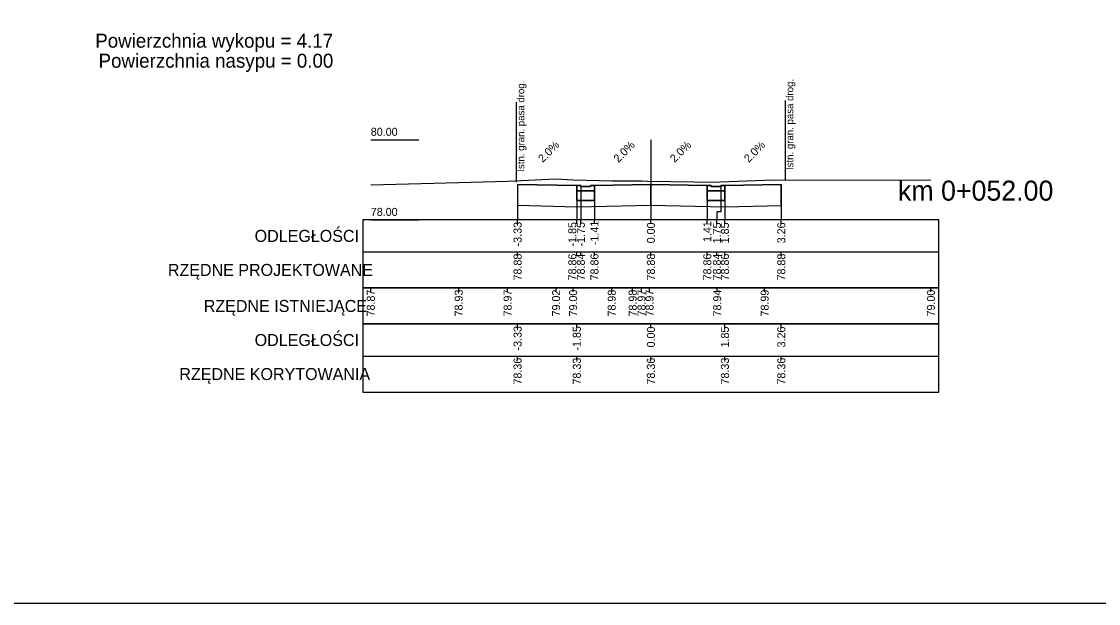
# Model space of a CAD drawing. Extents: x 7492871 to 7493499, y 5802964 to 5802992.
# Drawn here: x 7493013.99 to 7493040.9, y 5802963.88 to 5802978.41 of the extents above; entities that cross this region are included whole.
import ezdxf

# ---------------------------------------------------------------- set-up
doc = ezdxf.new("R2010")
doc.units = 0
for name, color, linetype in [('_wydruk', 7, 'Continuous'), ('d_pop_nasyp_opis', 7, 'Continuous'), ('d_pop_wykop_opis', 7, 'Continuous'), ('opisy_ramki_pop', 7, 'Continuous'), ('pop_comp_kostka', 7, 'Continuous'), ('pop_comp_lawa', 7, 'Continuous'), ('pop_comp_scieralna', 7, 'Continuous'), ('pop_granica_istn', 7, 'Continuous'), ('pop_opis', 7, 'Continuous'), ('pop_os', 7, 'Continuous'), ('pop_pikietaz', 7, 'Continuous'), ('pop_teren', 7, 'Continuous')]:
    doc.layers.add(name, color=color, linetype=linetype)

msp = doc.modelspace()

# ---------------------------------------------------------------- linework, layer by layer
msp.add_lwpolyline([(7493026.385, 5802974.344), (7493027.866, 5802974.314), (7493027.966, 5802974.314), (7493027.967, 5802974.294), (7493028.206, 5802974.294), (7493028.207, 5802974.314), (7493028.307, 5802974.314), (7493029.717, 5802974.343), (7493031.127, 5802974.314), (7493031.227, 5802974.314), (7493031.228, 5802974.294), (7493031.467, 5802974.294), (7493031.468, 5802974.314), (7493031.568, 5802974.314), (7493032.977, 5802974.343)])
at = {"layer": '_wydruk'}
msp.add_lwpolyline([(7492871.369, 5802992.281), (7493499.283, 5802992.281), (7493499.283, 5802963.881), (7492871.369, 5802963.881)], close=True, dxfattribs=at)
at = {"layer": 'opisy_ramki_pop'}
for points in [[(7493026.385, 5802973.824), (7493026.385, 5802973.659), (7493026.385, 5802973.659), (7493026.385, 5802973.459)], [(7493027.866, 5802973.785), (7493027.866, 5802973.659), (7493027.866, 5802973.659), (7493027.866, 5802973.459)], [(7493029.717, 5802973.823), (7493029.717, 5802973.659), (7493029.717, 5802973.659), (7493029.717, 5802973.459)], [(7493031.568, 5802973.785), (7493031.568, 5802973.659), (7493031.568, 5802973.659), (7493031.568, 5802973.459)], [(7493032.977, 5802973.822), (7493032.977, 5802973.659), (7493032.977, 5802973.659), (7493032.977, 5802973.459)]]:
    msp.add_lwpolyline(points, dxfattribs=at)
at = {"layer": 'pop_comp_kostka'}
for p, q in [((7493027.966, 5802974.314), (7493027.866, 5802974.314)), ((7493027.866, 5802974.314), (7493027.866, 5802974.184)), ((7493027.967, 5802974.294), (7493027.966, 5802974.314)), ((7493028.206, 5802974.294), (7493027.967, 5802974.294)), ((7493028.207, 5802974.314), (7493028.206, 5802974.294)), ((7493028.307, 5802974.314), (7493028.207, 5802974.314)), ((7493028.307, 5802974.184), (7493028.307, 5802974.314)), ((7493031.227, 5802974.314), (7493031.127, 5802974.314)), ((7493031.127, 5802974.314), (7493031.127, 5802974.184)), ((7493031.228, 5802974.294), (7493031.227, 5802974.314)), ((7493031.467, 5802974.294), (7493031.228, 5802974.294)), ((7493031.468, 5802974.314), (7493031.467, 5802974.294)), ((7493031.568, 5802974.314), (7493031.468, 5802974.314)), ((7493031.568, 5802974.184), (7493031.568, 5802974.314)), ((7493027.866, 5802974.184), (7493028.307, 5802974.184)), ((7493031.127, 5802974.184), (7493031.568, 5802974.184))]:
    msp.add_line(p, q, dxfattribs=at)
at = {"layer": 'pop_comp_lawa'}
for p, q in [((7493028.307, 5802974.184), (7493027.866, 5802974.184)), ((7493027.866, 5802974.184), (7493027.866, 5802973.944)), ((7493028.307, 5802973.944), (7493028.307, 5802974.184)), ((7493031.568, 5802974.184), (7493031.127, 5802974.184)), ((7493031.127, 5802974.184), (7493031.127, 5802973.944)), ((7493031.568, 5802973.944), (7493031.568, 5802974.184)), ((7493027.866, 5802973.944), (7493028.307, 5802973.944)), ((7493031.127, 5802973.944), (7493031.568, 5802973.944))]:
    msp.add_line(p, q, dxfattribs=at)
at = {"layer": 'pop_comp_scieralna'}
for p, q in [((7493027.866, 5802974.314), (7493026.385, 5802974.344)), ((7493026.385, 5802974.344), (7493026.385, 5802973.824)), ((7493027.866, 5802973.944), (7493027.866, 5802974.314)), ((7493029.717, 5802974.343), (7493028.307, 5802974.314)), ((7493028.307, 5802974.314), (7493028.307, 5802973.944)), ((7493029.717, 5802973.823), (7493029.717, 5802974.343)), ((7493031.127, 5802974.314), (7493029.717, 5802974.343)), ((7493029.717, 5802974.343), (7493029.717, 5802973.823)), ((7493031.127, 5802973.944), (7493031.127, 5802974.314)), ((7493032.977, 5802974.343), (7493031.568, 5802974.314)), ((7493031.568, 5802974.314), (7493031.568, 5802973.944)), ((7493032.977, 5802973.822), (7493032.977, 5802974.343)), ((7493026.385, 5802973.824), (7493027.866, 5802973.785)), ((7493028.307, 5802973.944), (7493027.866, 5802973.944)), ((7493027.866, 5802973.785), (7493029.717, 5802973.823)), ((7493029.717, 5802973.823), (7493031.568, 5802973.785)), ((7493031.568, 5802973.944), (7493031.127, 5802973.944)), ((7493031.568, 5802973.785), (7493032.977, 5802973.822))]:
    msp.add_line(p, q, dxfattribs=at)
at = {"layer": 'pop_granica_istn'}
for p, q in [((7493033.079, 5802974.943), (7493033.079, 5802976.443)), ((7493026.357, 5802974.901), (7493026.357, 5802976.401)), ((7493026.357, 5802974.401), (7493026.357, 5802974.901)), ((7493033.079, 5802974.443), (7493033.079, 5802974.943))]:
    msp.add_line(p, q, dxfattribs=at)
at = {"layer": 'pop_opis'}
for p, q in [((7493022.717, 5802975.459), (7493023.917, 5802975.459)), ((7493022.517, 5802973.459), (7493022.517, 5802971.759)), ((7493022.517, 5802973.459), (7493022.517, 5802971.759)), ((7493022.517, 5802973.459), (7493022.517, 5802971.759)), ((7493022.517, 5802973.459), (7493022.517, 5802971.759)), ((7493022.717, 5802973.459), (7493023.917, 5802973.459)), ((7493026.385, 5802973.359), (7493026.385, 5802973.459)), ((7493027.866, 5802973.359), (7493027.866, 5802973.459)), ((7493027.967, 5802973.359), (7493027.967, 5802973.459)), ((7493028.307, 5802973.359), (7493028.307, 5802973.459)), ((7493029.717, 5802973.359), (7493029.717, 5802973.459)), ((7493031.127, 5802973.359), (7493031.127, 5802973.459)), ((7493031.368, 5802973.359), (7493031.368, 5802973.459)), ((7493031.568, 5802973.359), (7493031.568, 5802973.459)), ((7493032.977, 5802973.359), (7493032.977, 5802973.459)), ((7493022.517, 5802972.659), (7493036.917, 5802972.659)), ((7493022.517, 5802972.659), (7493036.917, 5802972.659)), ((7493022.517, 5802972.659), (7493036.917, 5802972.659)), ((7493022.517, 5802972.659), (7493036.917, 5802972.659)), ((7493026.385, 5802972.559), (7493026.385, 5802972.659)), ((7493027.866, 5802972.559), (7493027.866, 5802972.659)), ((7493027.967, 5802972.559), (7493027.967, 5802972.659)), ((7493028.307, 5802972.559), (7493028.307, 5802972.659)), ((7493029.717, 5802972.559), (7493029.717, 5802972.659)), ((7493031.127, 5802972.559), (7493031.127, 5802972.659)), ((7493031.368, 5802972.559), (7493031.368, 5802972.659)), ((7493031.568, 5802972.559), (7493031.568, 5802972.659)), ((7493032.977, 5802972.559), (7493032.977, 5802972.659)), ((7493022.517, 5802971.759), (7493022.517, 5802970.859)), ((7493022.717, 5802971.659), (7493022.717, 5802971.759)), ((7493024.913, 5802971.659), (7493024.913, 5802971.759)), ((7493026.136, 5802971.659), (7493026.136, 5802971.759)), ((7493027.348, 5802971.659), (7493027.348, 5802971.759)), ((7493027.773, 5802971.659), (7493027.773, 5802971.759)), ((7493028.738, 5802971.659), (7493028.738, 5802971.759)), ((7493029.262, 5802971.659), (7493029.262, 5802971.759)), ((7493029.483, 5802971.659), (7493029.483, 5802971.759)), ((7493029.683, 5802971.659), (7493029.683, 5802971.759)), ((7493031.375, 5802971.659), (7493031.375, 5802971.759)), ((7493032.561, 5802971.659), (7493032.561, 5802971.759)), ((7493036.717, 5802971.659), (7493036.717, 5802971.759)), ((7493022.517, 5802970.859), (7493022.517, 5802969.159)), ((7493026.385, 5802970.759), (7493026.385, 5802970.859)), ((7493027.866, 5802970.759), (7493027.866, 5802970.859)), ((7493029.717, 5802970.759), (7493029.717, 5802970.859)), ((7493031.568, 5802970.759), (7493031.568, 5802970.859)), ((7493032.977, 5802970.759), (7493032.977, 5802970.859)), ((7493022.517, 5802970.059), (7493036.917, 5802970.059)), ((7493026.385, 5802969.959), (7493026.385, 5802970.059)), ((7493027.866, 5802969.959), (7493027.866, 5802970.059)), ((7493029.717, 5802969.959), (7493029.717, 5802970.059)), ((7493031.568, 5802969.959), (7493031.568, 5802970.059)), ((7493032.977, 5802969.959), (7493032.977, 5802970.059))]:
    msp.add_line(p, q, dxfattribs=at)
for points in [[(7493026.385, 5802974.344), (7493026.385, 5802973.659), (7493026.385, 5802973.659), (7493026.385, 5802973.459)], [(7493027.866, 5802974.314), (7493027.866, 5802973.659), (7493027.866, 5802973.659), (7493027.866, 5802973.459)], [(7493027.967, 5802974.294), (7493027.967, 5802973.659), (7493027.967, 5802973.659), (7493027.967, 5802973.459)], [(7493028.307, 5802974.314), (7493028.307, 5802973.659), (7493028.307, 5802973.659), (7493028.307, 5802973.459)], [(7493029.717, 5802974.343), (7493029.717, 5802973.659), (7493029.717, 5802973.659), (7493029.717, 5802973.459)], [(7493031.127, 5802974.314), (7493031.127, 5802973.659), (7493031.127, 5802973.659), (7493031.127, 5802973.459)], [(7493031.467, 5802974.294), (7493031.467, 5802973.659), (7493031.368, 5802973.659), (7493031.368, 5802973.459)], [(7493031.568, 5802974.314), (7493031.568, 5802973.659), (7493031.568, 5802973.659), (7493031.568, 5802973.459)], [(7493032.977, 5802974.343), (7493032.977, 5802973.659), (7493032.977, 5802973.659), (7493032.977, 5802973.459)]]:
    msp.add_lwpolyline(points, dxfattribs=at)
for points in [[(7493022.517, 5802973.459), (7493022.517, 5802971.759), (7493036.917, 5802971.759), (7493036.917, 5802973.459)], [(7493022.517, 5802973.459), (7493022.517, 5802971.759), (7493036.917, 5802971.759), (7493036.917, 5802973.459)], [(7493022.517, 5802973.459), (7493022.517, 5802971.759), (7493036.917, 5802971.759), (7493036.917, 5802973.459)], [(7493022.517, 5802973.459), (7493022.517, 5802971.759), (7493036.917, 5802971.759), (7493036.917, 5802973.459)], [(7493022.517, 5802971.759), (7493022.517, 5802970.859), (7493036.917, 5802970.859), (7493036.917, 5802971.759)], [(7493022.517, 5802970.859), (7493022.517, 5802969.159), (7493036.917, 5802969.159), (7493036.917, 5802970.859)]]:
    msp.add_lwpolyline(points, close=True, dxfattribs=at)
at = {"layer": 'pop_os'}
msp.add_line((7493029.717, 5802975.459), (7493029.717, 5802973.459), dxfattribs=at)
at = {"layer": 'pop_teren'}
msp.add_lwpolyline([(7493022.717, 5802974.332), (7493024.913, 5802974.389), (7493026.136, 5802974.428), (7493027.348, 5802974.484), (7493027.773, 5802974.455), (7493028.738, 5802974.438), (7493029.262, 5802974.436), (7493029.483, 5802974.433), (7493029.631, 5802974.429), (7493031.375, 5802974.402), (7493031.448, 5802974.408), (7493032.561, 5802974.448), (7493036.717, 5802974.458)], dxfattribs=at)

# ---------------------------------------------------------------- texts
at = {"layer": 'd_pop_nasyp_opis'}
msp.add_text('Powierzchnia nasypu = 0.00', height=0.35, dxfattribs=at).set_placement((7493015.912, 5802977.259))
at = {"layer": 'd_pop_wykop_opis'}
msp.add_text('Powierzchnia wykopu = 4.17', height=0.35, dxfattribs=at).set_placement((7493015.829, 5802977.759))
at = {"layer": 'pop_granica_istn'}
for p in [(7493033.278, 5802974.704), (7493026.555, 5802974.662)]:
    msp.add_text('Istn. gran. pasa drog.', height=0.18, rotation=90, dxfattribs=at).set_placement(p)
at = {"layer": 'pop_opis'}
for s, height, p in [('80.00', 0.2, (7493022.717, 5802975.559)), ('78.00', 0.2, (7493022.717, 5802973.559)), ('ODLEGŁOŚCI', 0.3, (7493019.813, 5802972.909)), ('ODLEGŁOŚCI', 0.3, (7493019.813, 5802972.909)), ('ODLEGŁOŚCI', 0.3, (7493019.813, 5802972.909)), ('ODLEGŁOŚCI', 0.3, (7493019.813, 5802972.909)), ('RZĘDNE PROJEKTOWANE', 0.3, (7493017.645, 5802972.059)), ('RZĘDNE PROJEKTOWANE', 0.3, (7493017.645, 5802972.059)), ('RZĘDNE PROJEKTOWANE', 0.3, (7493017.645, 5802972.059)), ('RZĘDNE PROJEKTOWANE', 0.3, (7493017.645, 5802972.059)), ('RZĘDNE ISTNIEJĄCE', 0.3, (7493018.542, 5802971.159)), ('ODLEGŁOŚCI', 0.3, (7493019.813, 5802970.309)), ('RZĘDNE KORYTOWANIA', 0.3, (7493017.931, 5802969.459))]:
    msp.add_text(s, height=height, dxfattribs=at).set_placement(p)
for s, rotation, p in [('2.0%', 45, (7493027.017, 5802974.879)), ('2.0%', 45, (7493028.903, 5802974.878)), ('2.0%', 45, (7493030.313, 5802974.878)), ('2.0%', 45, (7493032.164, 5802974.878)), ('-3.33', 90, (7493026.485, 5802972.798)), ('-1.85', 90, (7493027.853, 5802972.796)), ('-1.75', 90, (7493028.067, 5802972.796)), ('-1.41', 90, (7493028.407, 5802972.829)), ('0.00', 90, (7493029.817, 5802972.874)), ('1.41', 90, (7493031.227, 5802972.905)), ('1.75', 90, (7493031.468, 5802972.873)), ('1.85', 90, (7493031.668, 5802972.873)), ('3.26', 90, (7493033.077, 5802972.874)), ('78.88', 90, (7493026.485, 5802971.946)), ('78.86', 90, (7493027.853, 5802971.947)), ('78.84', 90, (7493028.067, 5802971.947)), ('78.86', 90, (7493028.407, 5802971.947)), ('78.88', 90, (7493029.817, 5802971.946)), ('78.86', 90, (7493031.227, 5802971.947)), ('78.84', 90, (7493031.468, 5802971.947)), ('78.86', 90, (7493031.668, 5802971.947)), ('78.88', 90, (7493033.077, 5802971.946)), ('78.87', 90, (7493022.817, 5802971.047)), ('78.93', 90, (7493025.013, 5802971.047)), ('78.97', 90, (7493026.236, 5802971.047)), ('79.02', 90, (7493027.448, 5802971.048)), ('79.00', 90, (7493027.873, 5802971.047)), ('78.98', 90, (7493028.838, 5802971.046)), ('78.98', 90, (7493029.362, 5802971.046)), ('78.97', 90, (7493029.583, 5802971.047)), ('78.97', 90, (7493029.783, 5802971.047)), ('78.94', 90, (7493031.475, 5802971.047)), ('78.99', 90, (7493032.661, 5802971.046)), ('79.00', 90, (7493036.817, 5802971.047)), ('-3.33', 90, (7493026.485, 5802970.198)), ('-1.85', 90, (7493027.966, 5802970.196)), ('0.00', 90, (7493029.817, 5802970.274)), ('1.85', 90, (7493031.668, 5802970.273)), ('3.26', 90, (7493033.077, 5802970.274)), ('78.36', 90, (7493026.485, 5802969.347)), ('78.33', 90, (7493027.966, 5802969.347)), ('78.36', 90, (7493029.817, 5802969.347)), ('78.33', 90, (7493031.668, 5802969.347)), ('78.36', 90, (7493033.077, 5802969.347))]:
    msp.add_text(s, height=0.2, rotation=rotation, dxfattribs=at).set_placement(p)
at = {"layer": 'pop_pikietaz'}
msp.add_text('km 0+052.00', height=0.5, dxfattribs=at).set_placement((7493035.893, 5802973.939))

doc.saveas('drawing.dxf')
